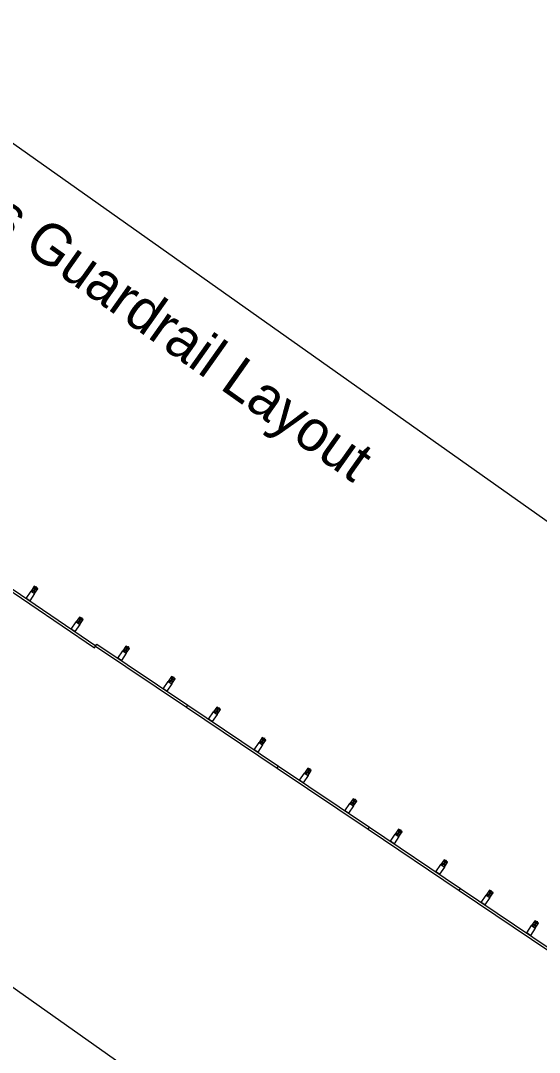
# Model space of a CAD drawing. Extents: x 16457860 to 16462445, y 6896068 to 6900243.
# Drawn here: x 16462137.4 to 16462196.7, y 6897892.8 to 6898010.7 of the extents above; entities that cross this region are included whole.
import ezdxf

# ---------------------------------------------------------------- set-up
doc = ezdxf.new("R2010")
doc.units = 0
doc.layers.add('Cell', color=7, linetype='Continuous')
doc.layers.add('Draft_DNC', color=7, linetype='Continuous')

msp = doc.modelspace()

# ---------------------------------------------------------------- linework, layer by layer
at = {"layer": 'Cell'}
for p, q in [((16462113.43, 6897961.43), (16462146.01, 6897939.28)), ((16462114.27, 6897960.53), (16462145.86, 6897939.05)), ((16462138.05, 6897944.69), (16462138.62, 6897945.52)), ((16462139.4, 6897945.79), (16462138.62, 6897945.52)), ((16462138.62, 6897945.52), (16462139.03, 6897945.24)), ((16462138.82, 6897945.38), (16462139.2, 6897945.93)), ((16462138.99, 6897946.07), (16462139.03, 6897945.24)), ((16462139.25, 6897946.01), (16462139.26, 6897946.01)), ((16462138.47, 6897944.41), (16462138.05, 6897944.69)), ((16462139.03, 6897945.24), (16462138.47, 6897944.41)), ((16462143.22, 6897941.18), (16462143.78, 6897942)), ((16462144.57, 6897942.27), (16462143.78, 6897942)), ((16462143.78, 6897942), (16462144.2, 6897941.72)), ((16462143.99, 6897941.86), (16462144.37, 6897942.41)), ((16462144.16, 6897942.55), (16462144.2, 6897941.72)), ((16462144.42, 6897942.49), (16462144.42, 6897942.5)), ((16462143.64, 6897940.89), (16462143.22, 6897941.18)), ((16462144.2, 6897941.72), (16462143.64, 6897940.89)), ((16462145.86, 6897939.05), (16462146.01, 6897939.28)), ((16462145.99, 6897939.24), (16462146.14, 6897939.47)), ((16462145.99, 6897939.24), (16462156.37, 6897932.27)), ((16462146.14, 6897939.47), (16462156.52, 6897932.49)), ((16462148.53, 6897937.86), (16462149.09, 6897938.69)), ((16462149.88, 6897938.97), (16462149.09, 6897938.69)), ((16462149.09, 6897938.69), (16462149.5, 6897938.41)), ((16462149.3, 6897938.55), (16462149.67, 6897939.11)), ((16462149.46, 6897939.24), (16462149.5, 6897938.41)), ((16462149.72, 6897939.19), (16462149.73, 6897939.19)), ((16462148.95, 6897937.58), (16462148.53, 6897937.86)), ((16462149.5, 6897938.41), (16462148.95, 6897937.58)), ((16462153.72, 6897934.37), (16462154.28, 6897935.2)), ((16462154.69, 6897934.93), (16462154.13, 6897934.09)), ((16462155.06, 6897935.48), (16462154.28, 6897935.2)), ((16462154.28, 6897935.2), (16462154.69, 6897934.93)), ((16462154.48, 6897935.06), (16462154.85, 6897935.62)), ((16462154.65, 6897935.76), (16462154.69, 6897934.93)), ((16462154.91, 6897935.7), (16462154.91, 6897935.7)), ((16462154.13, 6897934.09), (16462153.72, 6897934.37)), ((16462156.37, 6897932.27), (16462156.52, 6897932.49)), ((16462156.37, 6897932.27), (16462156.52, 6897932.49)), ((16462156.37, 6897932.27), (16462166.74, 6897925.29)), ((16462156.52, 6897932.49), (16462166.89, 6897925.52)), ((16462158.9, 6897930.89), (16462159.46, 6897931.72)), ((16462159.88, 6897931.44), (16462159.32, 6897930.61)), ((16462160.25, 6897931.99), (16462159.46, 6897931.72)), ((16462159.46, 6897931.72), (16462159.88, 6897931.44)), ((16462159.67, 6897931.58), (16462160.04, 6897932.13)), ((16462159.83, 6897932.27), (16462159.88, 6897931.44)), ((16462160.1, 6897932.21), (16462160.1, 6897932.22)), ((16462159.32, 6897930.61), (16462158.9, 6897930.89)), ((16462164.09, 6897927.4), (16462164.65, 6897928.23)), ((16462165.06, 6897927.95), (16462164.51, 6897927.12)), ((16462165.44, 6897928.5), (16462164.65, 6897928.23)), ((16462164.65, 6897928.23), (16462165.06, 6897927.95)), ((16462164.86, 6897928.09), (16462165.23, 6897928.64)), ((16462165.02, 6897928.78), (16462165.06, 6897927.95)), ((16462165.28, 6897928.72), (16462165.29, 6897928.73)), ((16462164.51, 6897927.12), (16462164.09, 6897927.4)), ((16462166.74, 6897925.29), (16462166.89, 6897925.52)), ((16462166.74, 6897925.29), (16462166.89, 6897925.52)), ((16462166.89, 6897925.52), (16462177.26, 6897918.54)), ((16462166.74, 6897925.29), (16462177.11, 6897918.32)), ((16462169.28, 6897923.91), (16462169.84, 6897924.74)), ((16462170.25, 6897924.46), (16462169.69, 6897923.63)), ((16462170.62, 6897925.02), (16462169.84, 6897924.74)), ((16462169.84, 6897924.74), (16462170.25, 6897924.46)), ((16462170.04, 6897924.6), (16462170.41, 6897925.16)), ((16462170.21, 6897925.3), (16462170.25, 6897924.46)), ((16462170.47, 6897925.24), (16462170.47, 6897925.24)), ((16462169.69, 6897923.63), (16462169.28, 6897923.91)), ((16462174.46, 6897920.42), (16462175.02, 6897921.26)), ((16462175.44, 6897920.98), (16462174.88, 6897920.15)), ((16462175.81, 6897921.53), (16462175.02, 6897921.26)), ((16462175.02, 6897921.26), (16462175.44, 6897920.98)), ((16462175.23, 6897921.12), (16462175.6, 6897921.67)), ((16462175.39, 6897921.81), (16462175.44, 6897920.98)), ((16462175.66, 6897921.75), (16462175.66, 6897921.76)), ((16462174.88, 6897920.15), (16462174.46, 6897920.42)), ((16462177.11, 6897918.32), (16462177.26, 6897918.54)), ((16462177.11, 6897918.32), (16462177.26, 6897918.54)), ((16462177.26, 6897918.54), (16462187.64, 6897911.57)), ((16462177.11, 6897918.32), (16462187.49, 6897911.34)), ((16462179.65, 6897916.94), (16462180.21, 6897917.77)), ((16462180.62, 6897917.49), (16462180.07, 6897916.66)), ((16462181, 6897918.04), (16462180.21, 6897917.77)), ((16462180.21, 6897917.77), (16462180.62, 6897917.49)), ((16462180.42, 6897917.63), (16462180.79, 6897918.18)), ((16462180.58, 6897918.32), (16462180.62, 6897917.49)), ((16462180.84, 6897918.26), (16462180.85, 6897918.27)), ((16462180.07, 6897916.66), (16462179.65, 6897916.94)), ((16462184.84, 6897913.45), (16462185.4, 6897914.28)), ((16462185.81, 6897914), (16462185.25, 6897913.17)), ((16462186.18, 6897914.56), (16462185.4, 6897914.28)), ((16462185.4, 6897914.28), (16462185.81, 6897914)), ((16462185.6, 6897914.14), (16462185.97, 6897914.69)), ((16462185.77, 6897914.83), (16462185.81, 6897914)), ((16462186.03, 6897914.78), (16462186.03, 6897914.78)), ((16462185.25, 6897913.17), (16462184.84, 6897913.45)), ((16462187.49, 6897911.34), (16462187.64, 6897911.57)), ((16462187.49, 6897911.34), (16462187.64, 6897911.57)), ((16462187.64, 6897911.57), (16462198.01, 6897904.59)), ((16462190.95, 6897911.35), (16462191, 6897910.51)), ((16462187.49, 6897911.34), (16462197.86, 6897904.37)), ((16462190.02, 6897909.96), (16462190.58, 6897910.79)), ((16462191, 6897910.51), (16462190.44, 6897909.68)), ((16462191.37, 6897911.07), (16462190.58, 6897910.79)), ((16462190.58, 6897910.79), (16462191, 6897910.51)), ((16462190.79, 6897910.65), (16462191.16, 6897911.21)), ((16462191.22, 6897911.29), (16462191.22, 6897911.29)), ((16462190.44, 6897909.68), (16462190.02, 6897909.96)), ((16462196.14, 6897907.86), (16462196.18, 6897907.03)), ((16462195.21, 6897906.48), (16462195.77, 6897907.31)), ((16462196.18, 6897907.03), (16462195.63, 6897906.2)), ((16462196.56, 6897907.58), (16462195.77, 6897907.31)), ((16462195.77, 6897907.31), (16462196.18, 6897907.03)), ((16462195.98, 6897907.17), (16462196.35, 6897907.72)), ((16462196.4, 6897907.8), (16462196.41, 6897907.81)), ((16462195.63, 6897906.2), (16462195.21, 6897906.48))]:
    msp.add_line(p, q, dxfattribs=at)
for points in [[(16462138.62, 6897945.52), (16462139.03, 6897945.24), (16462139.4, 6897945.79), (16462138.99, 6897946.07)], [(16462143.78, 6897942), (16462144.2, 6897941.72), (16462144.57, 6897942.27), (16462144.16, 6897942.55)], [(16462149.09, 6897938.69), (16462149.5, 6897938.41), (16462149.88, 6897938.97), (16462149.46, 6897939.24)], [(16462154.28, 6897935.2), (16462154.69, 6897934.93), (16462155.06, 6897935.48), (16462154.65, 6897935.76)], [(16462159.46, 6897931.72), (16462159.88, 6897931.44), (16462160.25, 6897931.99), (16462159.83, 6897932.27)], [(16462164.65, 6897928.23), (16462165.06, 6897927.95), (16462165.44, 6897928.5), (16462165.02, 6897928.78)], [(16462169.84, 6897924.74), (16462170.25, 6897924.46), (16462170.62, 6897925.02), (16462170.21, 6897925.3)], [(16462175.02, 6897921.26), (16462175.44, 6897920.98), (16462175.81, 6897921.53), (16462175.39, 6897921.81)], [(16462180.21, 6897917.77), (16462180.62, 6897917.49), (16462181, 6897918.04), (16462180.58, 6897918.32)], [(16462185.4, 6897914.28), (16462185.81, 6897914), (16462186.18, 6897914.56), (16462185.77, 6897914.83)], [(16462190.58, 6897910.79), (16462191, 6897910.51), (16462191.37, 6897911.07), (16462190.95, 6897911.35)], [(16462195.77, 6897907.31), (16462196.18, 6897907.03), (16462196.56, 6897907.58), (16462196.14, 6897907.86)]]:
    msp.add_lwpolyline(points, close=True, dxfattribs=at)
for points in [[(16462139.17, 6897945.95), (16462139.19, 6897945.98), (16462139.25, 6897945.95), (16462139.23, 6897945.91)], [(16462139.21, 6897945.97), (16462139.24, 6897946.02), (16462139.27, 6897946), (16462139.24, 6897945.95)], [(16462144.34, 6897942.43), (16462144.36, 6897942.47), (16462144.42, 6897942.43), (16462144.39, 6897942.4)], [(16462144.37, 6897942.46), (16462144.4, 6897942.51), (16462144.44, 6897942.48), (16462144.41, 6897942.44)], [(16462149.64, 6897939.12), (16462149.66, 6897939.16), (16462149.72, 6897939.12), (16462149.7, 6897939.09)], [(16462149.68, 6897939.15), (16462149.71, 6897939.2), (16462149.74, 6897939.18), (16462149.71, 6897939.13)], [(16462154.83, 6897935.64), (16462154.85, 6897935.67), (16462154.91, 6897935.64), (16462154.88, 6897935.6)], [(16462154.86, 6897935.66), (16462154.89, 6897935.71), (16462154.92, 6897935.69), (16462154.89, 6897935.64)], [(16462160.01, 6897932.15), (16462160.04, 6897932.19), (16462160.09, 6897932.15), (16462160.07, 6897932.11)], [(16462160.05, 6897932.18), (16462160.08, 6897932.22), (16462160.11, 6897932.2), (16462160.08, 6897932.16)], [(16462165.2, 6897928.66), (16462165.22, 6897928.7), (16462165.28, 6897928.66), (16462165.26, 6897928.62)], [(16462165.24, 6897928.69), (16462165.27, 6897928.74), (16462165.3, 6897928.71), (16462165.27, 6897928.67)], [(16462170.39, 6897925.17), (16462170.41, 6897925.21), (16462170.47, 6897925.17), (16462170.44, 6897925.14)], [(16462170.42, 6897925.2), (16462170.45, 6897925.25), (16462170.49, 6897925.23), (16462170.45, 6897925.18)], [(16462175.57, 6897921.69), (16462175.6, 6897921.72), (16462175.65, 6897921.69), (16462175.63, 6897921.65)], [(16462175.61, 6897921.72), (16462175.64, 6897921.76), (16462175.67, 6897921.74), (16462175.64, 6897921.69)], [(16462180.76, 6897918.2), (16462180.78, 6897918.24), (16462180.84, 6897918.2), (16462180.82, 6897918.16)], [(16462180.8, 6897918.23), (16462180.83, 6897918.27), (16462180.86, 6897918.25), (16462180.83, 6897918.21)], [(16462185.95, 6897914.71), (16462185.97, 6897914.75), (16462186.03, 6897914.71), (16462186, 6897914.68)], [(16462185.98, 6897914.74), (16462186.01, 6897914.79), (16462186.05, 6897914.76), (16462186.01, 6897914.72)], [(16462191.13, 6897911.23), (16462191.16, 6897911.26), (16462191.21, 6897911.22), (16462191.19, 6897911.19)], [(16462191.17, 6897911.25), (16462191.2, 6897911.3), (16462191.23, 6897911.28), (16462191.2, 6897911.23)], [(16462196.36, 6897907.77), (16462196.39, 6897907.81), (16462196.42, 6897907.79), (16462196.39, 6897907.74)], [(16462196.32, 6897907.74), (16462196.34, 6897907.77), (16462196.4, 6897907.74), (16462196.38, 6897907.7)]]:
    msp.add_lwpolyline(points, dxfattribs=at)
at = {"layer": 'Draft_DNC'}
msp.add_lwpolyline([(16462116.71, 6898010.67), (16462358.99, 6897839.26), (16462313.53, 6897775.01), (16462071.25, 6897946.41)], close=True, dxfattribs=at)

# ---------------------------------------------------------------- texts
msp.add_text('Previous Guardrail Layout', height=4.6875, rotation=324.7216, dxfattribs=at).set_placement((16462116.25, 6897999.69))

doc.saveas('drawing.dxf')
